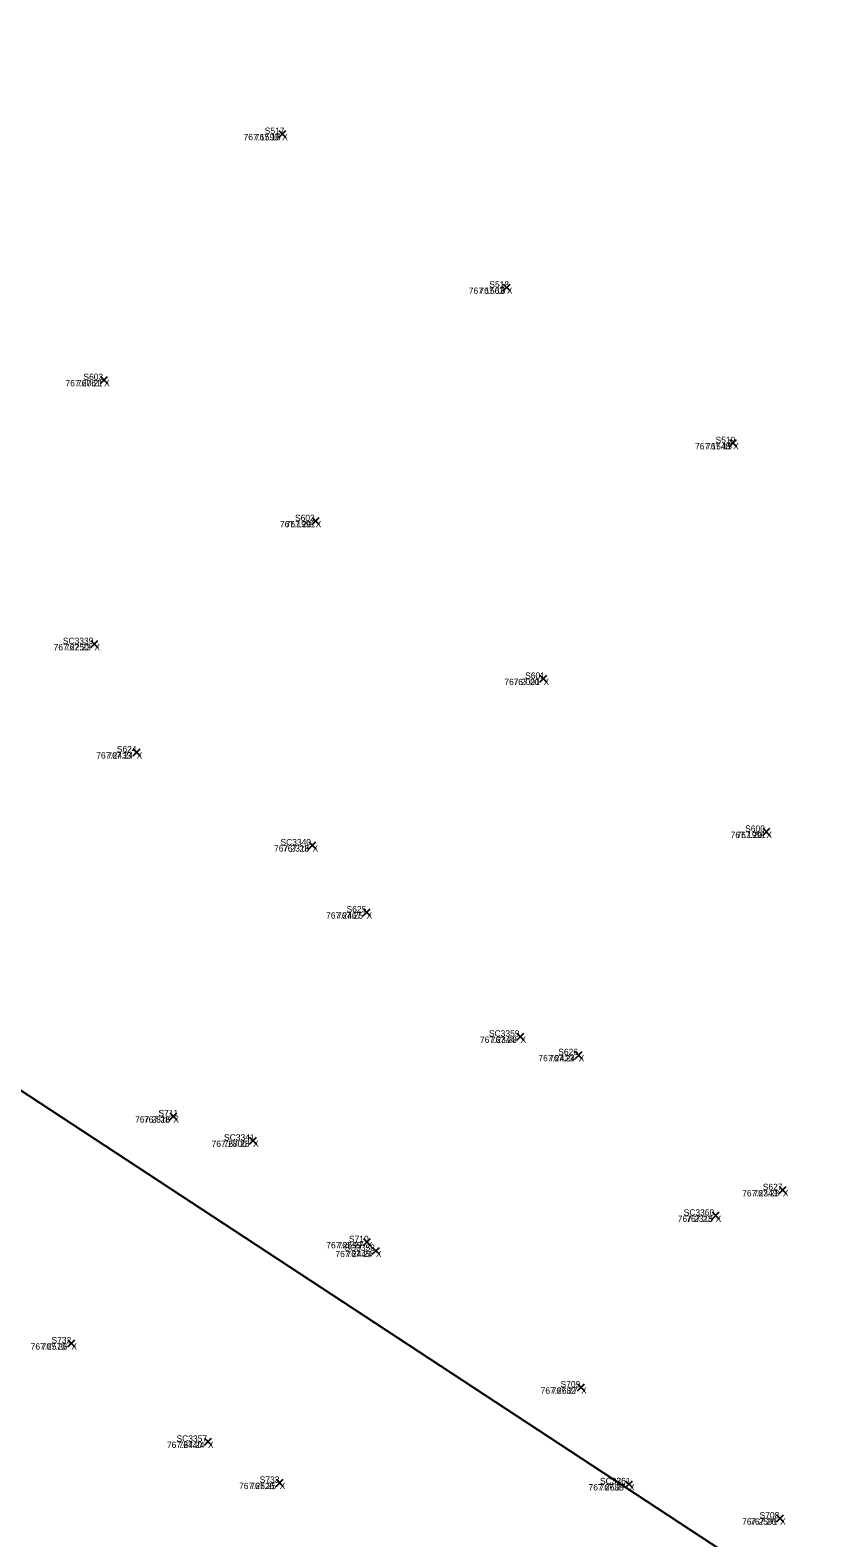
# Model space of a CAD drawing. Extents: x 1845019 to 1877956, y 680444 to 701081.
# Drawn here: x 1857738.9 to 1857746.31, y 694226.33 to 694240.65 of the extents above; entities that cross this region are included whole.
import ezdxf

# ---------------------------------------------------------------- set-up
doc = ezdxf.new("R2010")
doc.units = 0
for name, color, linetype in [('SV_X_CL_Survey_20', 7, 'Continuous'), ('SV_X_Random_Point', 7, 'Continuous'), ('SV_X_Text_Comment', 7, 'Continuous'), ('SV_X_Text_Elevation', 7, 'Continuous'), ('SV_X_Text_Name', 7, 'Continuous')]:
    doc.layers.add(name, color=color, linetype=linetype)

msp = doc.modelspace()

# ---------------------------------------------------------------- linework, layer by layer
at = {"layer": 'SV_X_CL_Survey_20'}
msp.add_line((1856038.267, 695346.314), (1858797.327, 693536.085), dxfattribs=at)
at = {"layer": 'SV_X_Random_Point'}
for p, q in [((1857741.26, 694239.632), (1857741.327, 694239.699)), ((1857741.26, 694239.699), (1857741.327, 694239.632)), ((1857741.26, 694239.632), (1857741.327, 694239.699)), ((1857741.26, 694239.699), (1857741.327, 694239.632)), ((1857743.393, 694238.174), (1857743.459, 694238.24)), ((1857743.393, 694238.24), (1857743.459, 694238.174)), ((1857743.393, 694238.174), (1857743.459, 694238.24)), ((1857743.393, 694238.24), (1857743.459, 694238.174)), ((1857739.569, 694237.296), (1857739.635, 694237.362)), ((1857739.569, 694237.362), (1857739.635, 694237.296)), ((1857739.569, 694237.296), (1857739.635, 694237.362)), ((1857739.569, 694237.362), (1857739.635, 694237.296)), ((1857745.541, 694236.696), (1857745.608, 694236.762)), ((1857745.541, 694236.762), (1857745.608, 694236.696)), ((1857745.541, 694236.696), (1857745.608, 694236.762)), ((1857745.541, 694236.762), (1857745.608, 694236.696)), ((1857741.578, 694235.956), (1857741.644, 694236.023)), ((1857741.578, 694236.023), (1857741.644, 694235.956)), ((1857741.578, 694235.956), (1857741.644, 694236.023)), ((1857741.578, 694236.023), (1857741.644, 694235.956)), ((1857739.477, 694234.788), (1857739.544, 694234.854)), ((1857739.477, 694234.854), (1857739.544, 694234.788)), ((1857739.477, 694234.788), (1857739.544, 694234.854)), ((1857739.477, 694234.854), (1857739.544, 694234.788)), ((1857743.741, 694234.458), (1857743.807, 694234.524)), ((1857743.741, 694234.524), (1857743.807, 694234.458)), ((1857743.741, 694234.458), (1857743.807, 694234.524)), ((1857743.741, 694234.524), (1857743.807, 694234.458)), ((1857739.879, 694233.759), (1857739.946, 694233.826)), ((1857739.879, 694233.826), (1857739.946, 694233.759)), ((1857739.879, 694233.759), (1857739.946, 694233.826)), ((1857739.879, 694233.826), (1857739.946, 694233.759)), ((1857745.857, 694233.004), (1857745.923, 694233.071)), ((1857745.857, 694233.071), (1857745.923, 694233.004)), ((1857745.857, 694233.004), (1857745.923, 694233.071)), ((1857745.857, 694233.071), (1857745.923, 694233.004)), ((1857741.547, 694232.876), (1857741.614, 694232.943)), ((1857741.547, 694232.943), (1857741.614, 694232.876)), ((1857741.547, 694232.876), (1857741.614, 694232.943)), ((1857741.547, 694232.943), (1857741.614, 694232.876)), ((1857742.061, 694232.24), (1857742.128, 694232.307)), ((1857742.061, 694232.307), (1857742.128, 694232.24)), ((1857742.061, 694232.24), (1857742.128, 694232.307)), ((1857742.061, 694232.307), (1857742.128, 694232.24)), ((1857743.521, 694231.06), (1857743.588, 694231.126)), ((1857743.521, 694231.126), (1857743.588, 694231.06)), ((1857743.521, 694231.06), (1857743.588, 694231.126)), ((1857743.521, 694231.126), (1857743.588, 694231.06)), ((1857744.075, 694230.883), (1857744.142, 694230.95)), ((1857744.075, 694230.95), (1857744.142, 694230.883)), ((1857744.075, 694230.883), (1857744.142, 694230.95)), ((1857744.075, 694230.95), (1857744.142, 694230.883)), ((1857740.227, 694230.302), (1857740.294, 694230.369)), ((1857740.227, 694230.369), (1857740.294, 694230.302)), ((1857740.227, 694230.302), (1857740.294, 694230.369)), ((1857740.227, 694230.369), (1857740.294, 694230.302)), ((1857740.984, 694230.071), (1857741.051, 694230.138)), ((1857740.984, 694230.138), (1857741.051, 694230.071)), ((1857740.984, 694230.071), (1857741.051, 694230.138)), ((1857740.984, 694230.138), (1857741.051, 694230.071)), ((1857746.012, 694229.602), (1857746.079, 694229.668)), ((1857746.012, 694229.668), (1857746.079, 694229.602)), ((1857746.012, 694229.602), (1857746.079, 694229.668)), ((1857746.012, 694229.668), (1857746.079, 694229.602)), ((1857745.376, 694229.36), (1857745.442, 694229.427)), ((1857745.376, 694229.427), (1857745.442, 694229.36)), ((1857745.376, 694229.36), (1857745.442, 694229.427)), ((1857745.376, 694229.427), (1857745.442, 694229.36)), ((1857742.064, 694229.108), (1857742.131, 694229.174)), ((1857742.064, 694229.174), (1857742.131, 694229.108)), ((1857742.064, 694229.108), (1857742.131, 694229.174)), ((1857742.064, 694229.174), (1857742.131, 694229.108)), ((1857742.149, 694229.025), (1857742.216, 694229.091)), ((1857742.149, 694229.091), (1857742.216, 694229.025)), ((1857742.149, 694229.025), (1857742.216, 694229.091)), ((1857742.149, 694229.091), (1857742.216, 694229.025)), ((1857739.259, 694228.147), (1857739.326, 694228.213)), ((1857739.259, 694228.213), (1857739.326, 694228.147)), ((1857739.259, 694228.147), (1857739.326, 694228.213)), ((1857739.259, 694228.213), (1857739.326, 694228.147)), ((1857744.097, 694227.728), (1857744.164, 694227.794)), ((1857744.097, 694227.794), (1857744.164, 694227.728)), ((1857744.097, 694227.728), (1857744.164, 694227.794)), ((1857744.097, 694227.794), (1857744.164, 694227.728)), ((1857740.555, 694227.212), (1857740.622, 694227.278)), ((1857740.555, 694227.278), (1857740.622, 694227.212)), ((1857740.555, 694227.212), (1857740.622, 694227.278)), ((1857740.555, 694227.278), (1857740.622, 694227.212)), ((1857741.236, 694226.821), (1857741.303, 694226.888)), ((1857741.236, 694226.888), (1857741.303, 694226.821)), ((1857741.236, 694226.821), (1857741.303, 694226.888)), ((1857741.236, 694226.888), (1857741.303, 694226.821)), ((1857744.553, 694226.809), (1857744.62, 694226.875)), ((1857744.553, 694226.875), (1857744.62, 694226.809)), ((1857744.553, 694226.809), (1857744.62, 694226.875)), ((1857744.553, 694226.875), (1857744.62, 694226.809)), ((1857745.987, 694226.483), (1857746.054, 694226.55)), ((1857745.987, 694226.55), (1857746.054, 694226.483)), ((1857745.987, 694226.483), (1857746.054, 694226.55)), ((1857745.987, 694226.55), (1857746.054, 694226.483))]:
    msp.add_line(p, q, dxfattribs=at)

# ---------------------------------------------------------------- texts
at = {"layer": 'SV_X_Text_Comment'}
for p in [(1857741.293, 694239.606), (1857743.426, 694238.147), (1857739.602, 694237.269), (1857745.575, 694236.669), (1857741.611, 694235.929), (1857739.51, 694234.761), (1857743.774, 694234.431), (1857739.912, 694233.733), (1857745.89, 694232.978), (1857741.581, 694232.85), (1857742.094, 694232.213), (1857743.555, 694231.033), (1857744.108, 694230.857), (1857740.26, 694230.276), (1857741.017, 694230.045), (1857746.046, 694229.575), (1857745.409, 694229.333), (1857742.097, 694229.081), (1857742.183, 694228.998), (1857739.292, 694228.12), (1857744.131, 694227.701), (1857740.588, 694227.185), (1857741.27, 694226.795), (1857744.586, 694226.782), (1857746.02, 694226.457)]:
    msp.add_text('X', height=0.06, dxfattribs=at).set_placement(p)
at = {"layer": 'SV_X_Text_Elevation'}
for s, p in [('767.1590', (1857740.927, 694239.606)), ('767.16', (1857741.033, 694239.606)), ('767.1563', (1857743.065, 694238.147)), ('767.16', (1857743.166, 694238.147)), ('767.2061', (1857739.236, 694237.269)), ('767.21', (1857739.345, 694237.269)), ('767.1548', (1857745.213, 694236.669)), ('767.15', (1857745.318, 694236.669)), ('767.1991', (1857741.272, 694235.929)), ('767.20', (1857741.327, 694235.929)), ('767.2250', (1857739.123, 694234.761)), ('767.23', (1857739.231, 694234.761)), ('767.2001', (1857743.403, 694234.431)), ('767.20', (1857743.49, 694234.431)), ('767.2433', (1857739.528, 694233.733)), ('767.24', (1857739.633, 694233.733)), ('767.1991', (1857745.551, 694232.978)), ('767.20', (1857745.606, 694232.978)), ('767.2316', (1857741.216, 694232.85)), ('767.23', (1857741.301, 694232.85)), ('767.2467', (1857741.71, 694232.213)), ('767.25', (1857741.815, 694232.213)), ('767.2344', (1857743.171, 694231.033)), ('767.23', (1857743.275, 694231.033)), ('767.2423', (1857743.726, 694230.857)), ('767.24', (1857743.829, 694230.857)), ('767.2816', (1857739.897, 694230.276)), ('767.28', (1857739.981, 694230.276)), ('767.2800', (1857740.623, 694230.045)), ('767.28', (1857740.738, 694230.045)), ('767.2343', (1857745.661, 694229.575)), ('767.23', (1857745.767, 694229.575)), ('767.2315', (1857745.049, 694229.333)), ('767.23', (1857745.13, 694229.333)), ('767.2699', (1857741.712, 694229.081)), ('767.27', (1857741.818, 694229.081)), ('767.2445', (1857741.799, 694228.998)), ('767.24', (1857741.904, 694228.998)), ('767.2570', (1857738.905, 694228.12)), ('767.26', (1857739.009, 694228.12)), ('767.2682', (1857743.747, 694227.701)), ('767.27', (1857743.852, 694227.701)), ('767.2440', (1857740.199, 694227.185)), ('767.24', (1857740.31, 694227.185)), ('767.2526', (1857740.884, 694226.795)), ('767.25', (1857740.99, 694226.795)), ('767.2688', (1857744.202, 694226.782)), ('767.27', (1857744.307, 694226.782)), ('767.2591', (1857745.66, 694226.457)), ('767.26', (1857745.737, 694226.457))]:
    msp.add_text(s, height=0.06, dxfattribs=at).set_placement(p)
at = {"layer": 'SV_X_Text_Name'}
for s, p in [('S517', (1857741.128, 694239.666)), ('S517', (1857741.128, 694239.666)), ('S518', (1857743.26, 694238.207)), ('S518', (1857743.26, 694238.207)), ('S603', (1857739.406, 694237.329)), ('S603', (1857739.406, 694237.329)), ('S519', (1857745.408, 694236.729)), ('S519', (1857745.408, 694236.729)), ('S602', (1857741.415, 694235.989)), ('S602', (1857741.415, 694235.989)), ('SC3339', (1857739.211, 694234.821)), ('SC3339', (1857739.211, 694234.821)), ('S601', (1857743.6, 694234.491)), ('S601', (1857743.601, 694234.491)), ('S624', (1857739.723, 694233.793)), ('S624', (1857739.723, 694233.793)), ('S600', (1857745.689, 694233.038)), ('S600', (1857745.689, 694233.038)), ('SC3340', (1857741.277, 694232.91)), ('SC3340', (1857741.277, 694232.91)), ('S625', (1857741.905, 694232.273)), ('S625', (1857741.905, 694232.273)), ('SC3359', (1857743.256, 694231.093)), ('SC3359', (1857743.256, 694231.093)), ('S626', (1857743.915, 694230.917)), ('S626', (1857743.915, 694230.917)), ('S711', (1857740.119, 694230.336)), ('S711', (1857740.118, 694230.336)), ('SC3341', (1857740.741, 694230.105)), ('SC3341', (1857740.742, 694230.105)), ('S627', (1857745.856, 694229.635)), ('S627', (1857745.856, 694229.635)), ('SC3360', (1857745.105, 694229.393)), ('SC3360', (1857745.105, 694229.393)), ('SC3358', (1857741.884, 694229.058)), ('SC3358', (1857741.884, 694229.058)), ('S710', (1857741.927, 694229.141)), ('S710', (1857741.927, 694229.141)), ('S732', (1857739.103, 694228.18)), ('S732', (1857739.103, 694228.18)), ('S709', (1857743.936, 694227.761)), ('S709', (1857743.936, 694227.761)), ('SC3357', (1857740.29, 694227.245)), ('SC3357', (1857740.29, 694227.245)), ('S733', (1857741.08, 694226.855)), ('S733', (1857741.08, 694226.855)), ('SC3361', (1857744.31, 694226.842)), ('SC3361', (1857744.311, 694226.842)), ('S708', (1857745.826, 694226.517)), ('S708', (1857745.826, 694226.517))]:
    msp.add_text(s, height=0.06, dxfattribs=at).set_placement(p)

doc.saveas('drawing.dxf')
